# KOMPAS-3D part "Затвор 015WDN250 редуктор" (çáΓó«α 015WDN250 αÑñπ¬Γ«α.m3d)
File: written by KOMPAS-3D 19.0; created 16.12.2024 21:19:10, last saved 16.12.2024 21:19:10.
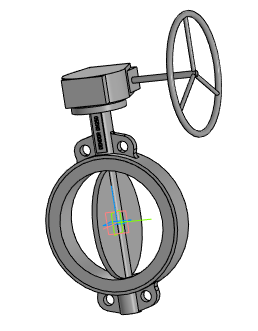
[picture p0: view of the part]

Document properties: Автор: Евгений; Полное имя файла: ..\Затвор 015WDN250 редуктор.a3d

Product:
- Part/product: Затвор 015WDN250 редуктор
    Масса: 39.2279

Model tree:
1. Операция без истории:1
